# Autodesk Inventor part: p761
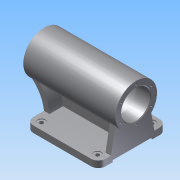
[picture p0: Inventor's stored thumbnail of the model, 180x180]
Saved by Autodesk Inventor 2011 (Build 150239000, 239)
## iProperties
Created: 2014-02
Part Number: p761
Document SubType Name: Modeling
Designer: Administrator
Density: 1 g/cm^3
Author: Administrator
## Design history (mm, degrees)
sketch "草图1"
  geometry: L1 (-100, 95)-(100, 95); L2 (100, 95)-(100, -95); L3 (100, -95)-(-100, -95); L4 (-100, -95)-(-100, 95); 3 further points
  constraints: 8 end point, 2 midpoint, 2 parallel, 1 horizontal, 1 horizontal alignment, 1 perpendicular, 1 vertical alignment
  dimensions: "d0" = 190 distance of L1.end L2.end; "d1" = 200 distance of L2.end L3.end
extrude "拉伸1" new body sketch "草图1" distance "d2" = 18; taper "d3" = 0 deg
sketch "草图2"
  geometry: C1 r 57.5 at (-115, 95); 1 further point
  constraints: 1 centre point
  dimensions: "d5" = 115 diameter of C1
extrude "拉伸2" join sketch "草图2" distance "d6" = 245; taper "d7" = 0 deg
sketch "草图3"
  geometry: C1 r 57.5 at (0, 0) reference; C2 r 57.5 at (0, 0); 1 further point
  constraints: 1 centre point, 1 coincident, 1 concentric
extrude "拉伸3" join sketch "草图3" distance "d8" = 10; taper "d9" = 0 deg
node "工作平面1"
node "工作平面2"
sketch "草图8"
  geometry: C1 r 57.5 at (0, 0) reference; C2 r 48 at (0, 0); 1 further point
  constraints: 1 centre point, 1 coincident
  dimensions: "d22" = 96 diameter of C2
extrude "拉伸5" cut sketch "草图8" stored distance "d23" = 175; taper "d24" = 0 deg
sketch "草图9"
  geometry: C1 r 57.5 at (0, 0) reference; C2 r 40 at (0, 0); 1 further point
  constraints: 1 centre point, 1 coincident
  dimensions: "d25" = 80 diameter of C2
extrude "拉伸6" cut sketch "草图9" stored distance "d26" = 175; taper "d27" = 0 deg
sketch "草图11" dims "d40" = 96
  geometry: C1 r 57.5 at (0, 0) reference; 3 further points
  constraints: 1 coincident, 1 horizontal alignment, 2 other
hole "Hole2" sketch "草图11" at (48, 0) diameter "d41" = 4.917; stored, may be unused: countersink angle "d45" = 90 deg, drill point angle "d47" = 118 deg; dims "d42" = 20, "d43" = 4, "d44" = 2, "d46" = 22
sketch "草图12"
  geometry: L1 (-110, 172.5)-(145, 172.5) reference; L2 (-110, 75)-(-110, 155) reference; L3 (-141.709, 115)-(17.5, 115); L4 (-110, 57.5)-(-110, 172.5) reference; L5 (191.981, 115)-(17.5, 115); 1 further point
  constraints: 4 end point, 2 perpendicular
pattern_circular "环形阵列1" dims angle "d49" = 360 deg
sketch "草图13"
  geometry: C1 r 57.5 at (0, 0) reference; C2 r 48 at (0, 0); C3 r 2.458 at (48, 0) reference; 2 further points
  constraints: 2 coincident, 1 centre point
  dimensions: "d51" = 96 diameter of C2
hole "Hole3" sketch "草图13" at (48, 0) diameter "d52" = 6.647; stored, may be unused: countersink angle "d56" = 90 deg, drill point angle "d58" = 118 deg; dims "d53" = 20, "d54" = 4, "d55" = 2, "d57" = 22
sketch "草图14"
  geometry: L1 (164.369, 115)-(127.582, 115); L2 (145, 172.5)-(145, 57.5) reference; 1 further point
  constraints: 2 end point, 1 perpendicular
pattern_circular "环形阵列2" dims angle "d60" = 360 deg
chamfer "倒角1" distance "d62" = 2; stored, may be unused: second distance "d63" = 2, angle "d64" = 45 deg
chamfer "倒角2" distance "d65" = 2; stored, may be unused: second distance "d66" = 2, angle "d67" = 45 deg
sketch "草图15"
  geometry: L1 (-100, 95)-(-100, -95) reference; L2 (-100, -55)-(100, -55); L3 (100, -55)-(100, 55); L4 (100, 55)-(-100, 55); L5 (-100, 55)-(-100, -55); 2 further points
  constraints: 8 end point, 2 midpoint, 2 parallel, 1 horizontal, 1 perpendicular
  dimensions: "d68" = 110 distance of L4.end L2.start; "d69" = 200 distance of L3.end L4.end
extrude "拉伸8" cut sketch "草图15" distance "d70" = 5; taper "d71" = 0 deg
fillet "圆角3" dims "d72" = 20
hole "Hole4" diameter "d75" = 11; stored, may be unused: countersink angle "d79" = 90 deg, drill point angle "d81" = 118 deg; dims "d73" = 22.5, "d74" = 20, "d76" = 6, "d77" = 22, "d78" = 2, "d80" = 8
mirror "镜像1"
mirror "镜像2"
sketch "草图17"
  geometry: L1 (-13, 130)-(-13, -20) reference; L2 (-13, -5)-(-78.342, 7); L3 (-7.872, 55)-(-99.249, 55); L4 (-13, 115)-(-78.342, 103); L5 (-13, -5)-(-13, 115); A1 r 57.5 centre (-110, 55) between (-78.342, 7) and (-78.342, 103); A2 r 57.5 centre (-110, 55) between (-78.342, 7) and (-78.342, 103); 2 further points
  constraints: 8 end point, 4 point on circle, 2 centre point, 2 symmetric about line, 1 coincident, 1 collinear, 1 horizontal alignment, 1 midpoint, 1 perpendicular, 1 point on line
  dimensions: "d83" = 96 distance of L4.end L2.end; "d84" = 120 distance of L4.start L2.start
extrude "拉伸9" join sketch "草图17" distance "d85" = 15; taper "d86" = 0 deg
sketch "草图18"
  geometry: L1 (-110, 57.5)-(145, 57.5) reference; L2 (80, 18)-(100, 18) reference; L3 (100, 18)-(100, 0) reference; L4 (100, 0)-(-100, 0) reference; L5 (108.846, 6)-(194.81, 6); L6 (-100, 5)-(100, 5) reference; L7 (112.296, 81.23)-(137.205, 81.23); A1 r 110 centre (194.239, 6) between (113.987, 81.23) and (84.896, 18); A2 r 95 centre (194.239, 6) between (136.226, 81.23) and (100, 18); 4 further points
  constraints: 8 point on line, 5 end point, 4 point on circle, 2 centre point, 2 parallel, 1 coincident
  dimensions: "d87" = 6 distance between parallel lines of L4 L5; "d94" = 220 diameter of A1; "d95" = 190 diameter of A2
extrude "拉伸11" join sketch "草图18" stored distance "d96" = 90; taper "d97" = 0 deg
hole "Hole5" diameter "d100" = 80; stored, may be unused: countersink angle "d104" = 90 deg, drill point angle "d106" = 118 deg; dims "d98" = 10, "d99" = 10, "d101" = 6, "d102" = 22, "d103" = 2, "d105" = 8
hole "Hole6" diameter "d109" = 96; stored, may be unused: countersink angle "d113" = 90 deg, drill point angle "d115" = 0 deg; dims "d107" = 10, "d108" = 10, "d110" = 6, "d111" = 22, "d112" = 2, "d114" = 175
hole "Hole7" diameter "d118" = 6.647; stored, may be unused: countersink angle "d122" = 90 deg, drill point angle "d124" = 120 deg; dims "d116" = 10, "d117" = 10, "d119" = 20, "d120" = 22, "d121" = 2, "d123" = 22
sketch "草图19"
  geometry: L1 (-85, 83.342)-(-85, 18) reference; L2 (-88.5, 18)-(-66.5, 18) reference; L3 (-80, 18)-(80, 18) reference; L4 (66.5, 18)-(88.5, 18) reference; L5 (-85, 63.388)-(100.395, 63.388); A1 r 110 centre (194.239, 6) between (112.136, 79.205) and (84.896, 18) reference; 1 further point
  constraints: 2 end point, 1 parallel, 1 point on circle, 1 point on line
extrude "拉伸12" join sketch "草图19" stored distance "d125" = 15; taper "d126" = 0 deg
node "实体1"
other parameters: "d16" = 57.5
